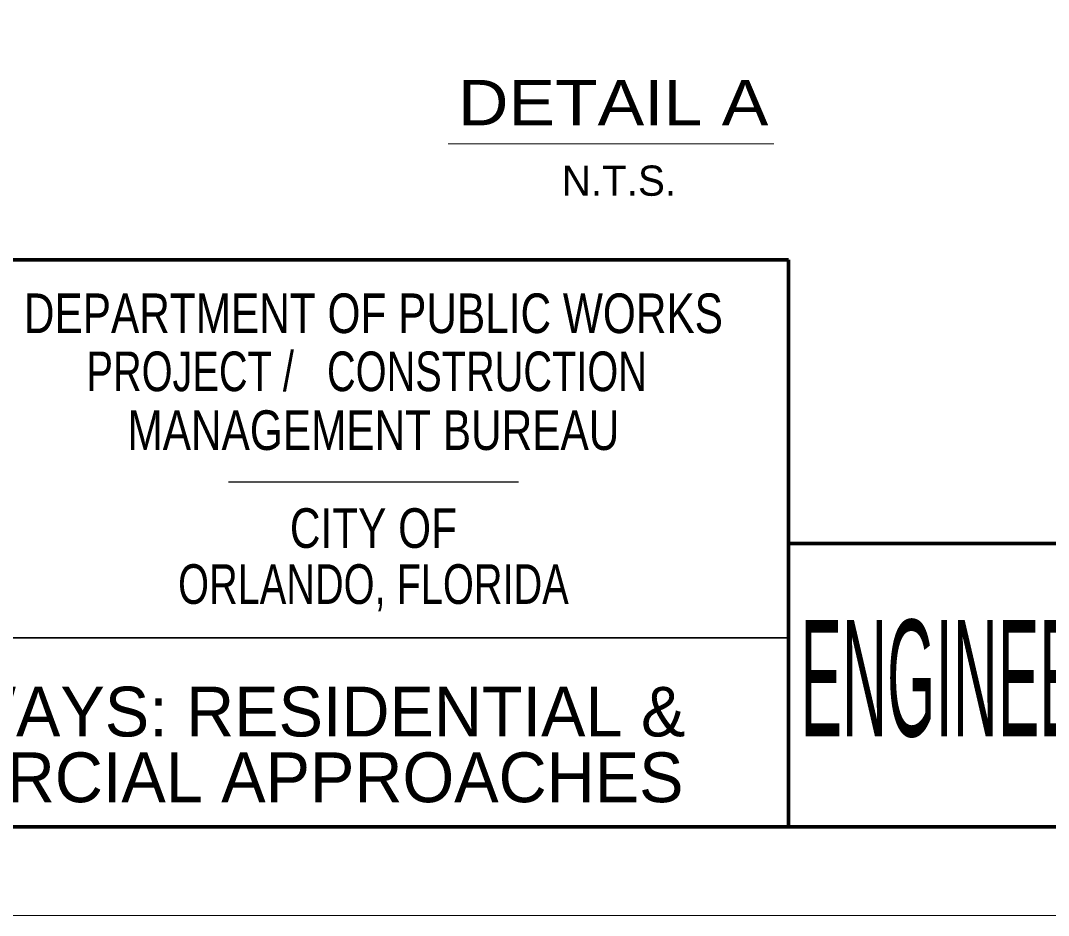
# Model space of a CAD drawing. Extents: x 124.7 to 141.7, y -6.7 to 4.3.
# Drawn here: x 126.905 to 129.626, y -6.708 to -4.341 of the extents above; entities that cross this region are included whole.
import ezdxf
from ezdxf.enums import TextEntityAlignment as Align

# ---------------------------------------------------------------- set-up
doc = ezdxf.new("R2010")
doc.units = 0
doc.header["$LTSCALE"] = 0.033
for name, color, linetype, lineweight in [('6', 7, 'Continuous', 13), ('60', 7, 'Continuous', 13), ('7', 7, 'Continuous', 13)]:
    doc.layers.add(name, color=color, linetype=linetype, lineweight=lineweight)
doc.layers.add('62', color=7, linetype='Continuous')

msp = doc.modelspace()

# ---------------------------------------------------------------- linework, layer by layer
at = {"layer": '60', "lineweight": 70}
for p, q in [((128.93787, -4.97445), (124.91782, -4.97445)), ((128.93787, -6.47409), (128.93787, -4.97445))]:
    msp.add_line(p, q, dxfattribs=at)
at = {"layer": '60', "lineweight": 25}
msp.add_line((128.22285, -5.56221), (127.45565, -5.56221), dxfattribs=at)
at = {"layer": '60', "lineweight": 35}
msp.add_line((128.93787, -5.97418), (125.96071, -5.97418), dxfattribs=at)
at = {"layer": '60'}
msp.add_lwpolyline([(141.66697, -6.70846), (124.65648, -6.70846), (124.65648, 4.29833), (141.66697, 4.29833)], close=True, dxfattribs=at)
at = {"layer": '60', "lineweight": 70}
msp.add_lwpolyline([(140.98583, 4.08146), (124.91782, 4.08146), (124.91782, -6.47409), (140.98583, -6.47409)], close=True, dxfattribs=at)
msp.add_lwpolyline([(134.05352, -6.47397), (134.05352, -5.72428), (128.93787, -5.72428)], dxfattribs=at)
at = {"layer": '7'}
msp.add_line((128.03691, -4.66759), (128.89855, -4.66759), dxfattribs=at)

# ---------------------------------------------------------------- texts
at = {"layer": '6'}
msp.add_text('N.T.S.', height=0.07992, dxfattribs=at).set_placement((128.33752, -4.80479))
at = {"layer": '60'}
for s, height, width, p in [('DEPARTMENT OF PUBLIC WORKS', 0.1048, 0.8, (127.83922, -5.16804)), ('PROJECT /   CONSTRUCTION', 0.1048, 0.75, (127.82146, -5.32163)), ('MANAGEMENT BUREAU', 0.1048, 0.8, (127.83923, -5.47724)), ('CITY OF', 0.1048, 0.8, (127.83926, -5.73626)), ('ORLANDO, FLORIDA', 0.1048, 0.75, (127.83923, -5.88439)), ('ENGINEERING STANDARDS MANUAL', 0.3082, 0.4, (130.44425, -6.2348))]:
    msp.add_text(s, height=height, dxfattribs=dict(at, width=width)).set_placement(p, align=Align.CENTER)
at = {"layer": '62'}
for s, p in [('DRIVEWAYS: RESIDENTIAL &', (127.42684, -6.23504)), ('COMMERCIAL APPROACHES', (127.42684, -6.40896))]:
    msp.add_text(s, height=0.1317, dxfattribs=at).set_placement(p, align=Align.CENTER)
at = {"layer": '7', "width": 1.15}
msp.add_text('DETAIL A', height=0.1201, dxfattribs=at).set_placement((128.06327, -4.6184))

doc.saveas('drawing.dxf')
